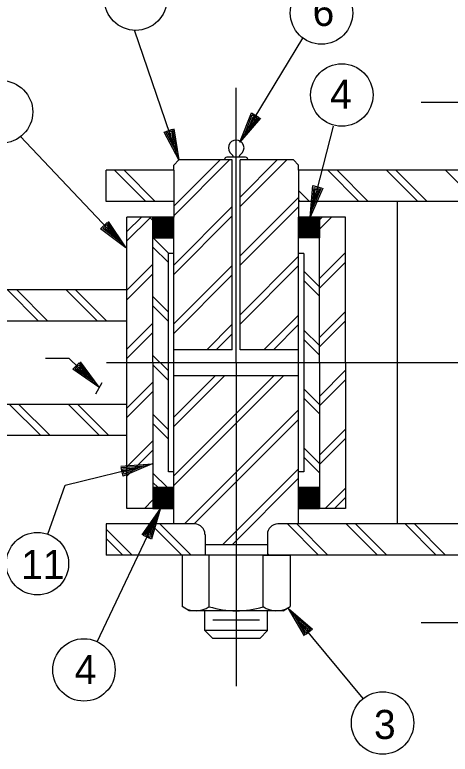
# Model space of a CAD drawing. Extents: x -0.2 to 13.5, y -0.2 to 9.5.
# Drawn here: x 2.351 to 3.223, y 1.127 to 2.607 of the extents above; entities that cross this region are included whole.
import ezdxf

# ---------------------------------------------------------------- set-up
doc = ezdxf.new("R2010")
doc.units = 0
for name, color, linetype in [('Level 2', 7, 'Continuous'), ('Level 3', 7, 'Continuous'), ('Level 50', 7, 'Continuous')]:
    doc.layers.add(name, color=color, linetype=linetype)

msp = doc.modelspace()

# ---------------------------------------------------------------- linework, layer by layer
at = {"layer": 'Level 2'}
for p, q in [((2.7941, 1.9106), (2.7941, 2.4612)), ((4.7037, 2.4315), (3.1643, 2.4315)), ((2.6795, 2.3169), (2.6691, 2.3065)), ((2.7863, 2.3169), (2.6795, 2.3169)), ((2.7709, 2.3169), (2.7709, 2.3179)), ((2.813, 2.322), (2.775, 2.322)), ((2.7863, 1.9367), (2.7863, 2.3169)), ((2.7941, 2.322), (2.7941, 2.322)), ((2.7941, 2.322), (2.7941, 2.322)), ((2.8019, 1.9367), (2.8019, 2.3169)), ((2.9086, 2.3169), (2.8019, 2.3169)), ((2.8172, 2.3169), (2.8172, 2.3179)), ((2.9086, 2.3169), (2.9191, 2.3065)), ((2.5336, 2.2336), (2.5336, 2.2961)), ((2.6691, 2.2961), (2.5336, 2.2961)), ((2.6691, 2.2961), (2.6691, 2.3065)), ((2.6691, 2.2961), (2.6691, 2.2023)), ((2.9191, 2.2961), (2.9191, 2.3065)), ((2.9191, 2.2961), (2.9191, 2.2023)), ((3.4503, 2.2961), (2.9191, 2.2961)), ((2.6691, 2.2336), (2.5336, 2.2336)), ((3.4503, 2.2336), (2.9191, 2.2336)), ((3.117, 1.5877), (3.117, 2.2336)), ((2.5753, 1.619), (2.5753, 2.2023)), ((2.6691, 2.2023), (2.5753, 2.2023)), ((2.6274, 1.9106), (2.6274, 2.2023)), ((2.6691, 1.5877), (2.6691, 2.2023)), ((3.0128, 2.2023), (2.9191, 2.2023)), ((2.9191, 1.5877), (2.9191, 2.2023)), ((2.9607, 1.9106), (2.9607, 2.2023)), ((3.0128, 1.9106), (3.0128, 2.2023)), ((2.6691, 2.1606), (2.6274, 2.1606)), ((2.9607, 2.1606), (2.9191, 2.1606)), ((2.6586, 1.6919), (2.6586, 2.1294)), ((2.6691, 2.1294), (2.6586, 2.1294)), ((2.9295, 2.1294), (2.9191, 2.1294)), ((2.9295, 2.1294), (2.9295, 1.6919)), ((2.5753, 2.0565), (2.1899, 2.0565)), ((2.5753, 1.994), (2.1899, 1.994)), ((2.7863, 1.9367), (2.6691, 1.9367)), ((2.9191, 1.9367), (2.8019, 1.9367)), ((4.53, 1.9106), (2.534, 1.9106)), ((2.6274, 1.9106), (2.6274, 1.619)), ((2.7941, 1.9106), (2.7941, 1.2627)), ((2.9607, 1.9106), (2.9607, 1.619)), ((3.0128, 1.9106), (3.0128, 1.619)), ((2.9191, 1.8846), (2.6691, 1.8846)), ((2.5753, 1.8273), (2.1899, 1.8273)), ((2.5753, 1.7648), (2.1899, 1.7648)), ((2.6691, 1.6919), (2.6586, 1.6919)), ((2.9295, 1.6919), (2.9191, 1.6919)), ((2.6691, 1.6606), (2.6274, 1.6606)), ((2.9607, 1.6606), (2.9191, 1.6606)), ((2.6691, 1.619), (2.5753, 1.619)), ((3.0128, 1.619), (2.9191, 1.619)), ((2.5336, 1.5877), (2.5336, 1.5252)), ((2.7107, 1.5877), (2.5336, 1.5877)), ((3.4503, 1.5877), (2.8774, 1.5877)), ((2.7316, 1.5669), (2.7316, 1.5252)), ((2.8566, 1.5669), (2.8566, 1.5252)), ((2.8566, 1.5461), (2.7316, 1.5461)), ((3.4503, 1.5252), (2.5336, 1.5252)), ((2.9503, 1.5252), (2.6378, 1.5252)), ((2.6857, 1.5252), (2.6857, 1.4224)), ((2.7398, 1.4221), (2.7398, 1.5252)), ((2.8476, 1.5252), (2.9024, 1.5252)), ((2.8483, 1.4221), (2.8483, 1.5252)), ((2.9024, 1.5252), (2.9024, 1.4224)), ((2.7002, 1.4139), (2.6857, 1.4224)), ((2.8879, 1.4139), (2.9024, 1.4224)), ((2.8879, 1.4139), (2.7002, 1.4139)), ((2.7313, 1.3742), (2.7313, 1.4139)), ((2.8568, 1.3742), (2.8568, 1.4139)), ((2.8409, 1.3953), (2.7476, 1.3953)), ((4.7037, 1.3898), (3.1643, 1.3898)), ((2.7313, 1.3742), (2.747, 1.3586)), ((2.8568, 1.3742), (2.7313, 1.3742)), ((2.8568, 1.3742), (2.8411, 1.3586)), ((2.8411, 1.3586), (2.747, 1.3586)), ((2.8411, 1.3586), (2.747, 1.3586)), ((2.8409, 1.3586), (2.7476, 1.3586))]:
    msp.add_line(p, q, dxfattribs=at)
for points in [[(2.6691, 2.2051), (2.7808, 2.3169)], [(2.6691, 2.224), (2.7619, 2.3169)], [(2.8019, 2.2236), (2.8952, 2.3169)], [(2.8019, 2.2424), (2.8763, 2.3169)], [(2.613, 2.2336), (2.5505, 2.2961)], [(2.6319, 2.2336), (2.5694, 2.2961)], [(2.6691, 2.2953), (2.6684, 2.2961)], [(3.0398, 2.2335), (2.9773, 2.2961)], [(3.0587, 2.2335), (2.9962, 2.2961)], [(3.1577, 2.2336), (3.0952, 2.2961)], [(3.1766, 2.2336), (3.114, 2.2961)], [(3.2755, 2.2336), (3.213, 2.2961)], [(2.9408, 2.2336), (2.9191, 2.2553)], [(2.8019, 2.1246), (2.9191, 2.2418)], [(2.922, 2.2335), (2.9191, 2.2365)], [(2.6691, 2.1061), (2.7863, 2.2233)], [(2.8019, 2.1057), (2.9191, 2.2229)], [(2.5753, 2.1546), (2.6231, 2.2023)], [(2.5753, 2.1734), (2.6042, 2.2023)], [(2.6274, 2.1955), (2.6206, 2.2023)], [(2.6274, 2.2017), (2.6691, 2.2017)], [(2.6274, 2.2005), (2.6691, 2.2005)], [(2.6274, 2.1992), (2.6691, 2.1992)], [(2.6274, 2.198), (2.6691, 2.198)], [(2.6274, 2.1967), (2.6691, 2.1967)], [(2.6274, 2.1955), (2.6691, 2.1955)], [(2.6274, 2.1942), (2.6691, 2.1942)], [(2.6274, 2.193), (2.6691, 2.193)], [(2.6274, 2.1917), (2.6691, 2.1917)], [(2.6691, 2.0873), (2.7863, 2.2045)], [(2.9191, 2.2018), (2.9607, 2.2018)], [(2.9191, 2.2005), (2.9607, 2.2005)], [(2.9191, 2.1993), (2.9607, 2.1993)], [(2.9191, 2.198), (2.9607, 2.198)], [(2.9191, 2.1968), (2.9607, 2.1968)], [(2.9191, 2.1955), (2.9607, 2.1955)], [(2.9191, 2.1943), (2.9607, 2.1943)], [(2.9191, 2.193), (2.9607, 2.193)], [(2.9191, 2.1918), (2.9607, 2.1918)], [(2.9607, 2.178), (2.985, 2.2023)], [(2.9607, 2.1969), (2.9661, 2.2023)], [(2.6274, 2.1905), (2.6691, 2.1905)], [(2.6274, 2.1892), (2.6691, 2.1892)], [(2.6274, 2.188), (2.6691, 2.188)], [(2.6274, 2.1867), (2.6691, 2.1867)], [(2.6274, 2.1855), (2.6691, 2.1855)], [(2.6274, 2.1842), (2.6691, 2.1842)], [(2.6274, 2.183), (2.6691, 2.183)], [(2.6274, 2.1817), (2.6691, 2.1817)], [(2.6274, 2.1805), (2.6691, 2.1805)], [(2.6274, 2.1792), (2.6691, 2.1792)], [(2.6274, 2.178), (2.6691, 2.178)], [(2.6274, 2.1767), (2.6691, 2.1767)], [(2.9191, 2.1905), (2.9607, 2.1905)], [(2.9191, 2.1893), (2.9607, 2.1893)], [(2.9191, 2.188), (2.9607, 2.188)], [(2.9191, 2.1868), (2.9607, 2.1868)], [(2.9191, 2.1855), (2.9607, 2.1855)], [(2.9191, 2.1843), (2.9607, 2.1843)], [(2.9191, 2.183), (2.9607, 2.183)], [(2.9191, 2.1818), (2.9607, 2.1818)], [(2.9191, 2.1805), (2.9607, 2.1805)], [(2.9191, 2.1793), (2.9607, 2.1793)], [(2.9191, 2.178), (2.9607, 2.178)], [(2.9191, 2.1768), (2.9607, 2.1768)], [(2.6274, 2.1755), (2.6691, 2.1755)], [(2.6274, 2.1742), (2.6691, 2.1742)], [(2.6274, 2.173), (2.6691, 2.173)], [(2.6274, 2.1717), (2.6691, 2.1717)], [(2.6274, 2.1705), (2.6691, 2.1705)], [(2.6274, 2.1692), (2.6691, 2.1692)], [(2.6274, 2.168), (2.6691, 2.168)], [(2.6274, 2.1667), (2.6691, 2.1667)], [(2.6274, 2.1655), (2.6691, 2.1655)], [(2.6274, 2.1642), (2.6691, 2.1642)], [(2.6274, 2.163), (2.6691, 2.163)], [(2.9191, 2.1755), (2.9607, 2.1755)], [(2.9191, 2.1743), (2.9607, 2.1743)], [(2.9191, 2.173), (2.9607, 2.173)], [(2.9191, 2.1718), (2.9607, 2.1718)], [(2.9191, 2.1705), (2.9607, 2.1705)], [(2.9191, 2.1693), (2.9607, 2.1693)], [(2.9191, 2.168), (2.9607, 2.168)], [(2.9191, 2.1668), (2.9607, 2.1668)], [(2.9191, 2.1655), (2.9607, 2.1655)], [(2.9191, 2.1643), (2.9607, 2.1643)], [(2.9191, 2.163), (2.9607, 2.163)], [(2.9191, 2.1618), (2.9607, 2.1618)], [(2.6274, 2.1617), (2.6691, 2.1617)], [(2.6591, 2.1294), (2.6279, 2.1606)], [(2.6586, 2.111), (2.6274, 2.1423)], [(2.8019, 2.0067), (2.9191, 2.1239)], [(2.9607, 2.079), (3.0128, 2.1311)], [(2.5753, 2.0556), (2.6274, 2.1077)], [(2.6691, 1.9883), (2.7863, 2.1055)], [(2.8019, 1.9879), (2.9191, 2.1051)], [(2.9607, 2.0602), (3.0128, 2.1123)], [(2.5753, 2.0367), (2.6274, 2.0888)], [(2.9607, 2.0627), (2.9295, 2.0939)], [(2.6691, 1.9694), (2.7863, 2.0866)], [(2.9607, 2.0438), (2.9295, 2.0751)], [(2.3982, 1.994), (2.3357, 2.0565)], [(2.417, 1.994), (2.3545, 2.0565)], [(2.516, 1.994), (2.4535, 2.0565)], [(2.5349, 1.994), (2.4724, 2.0565)], [(2.6586, 2.012), (2.6274, 2.0433)], [(2.6586, 1.9931), (2.6274, 2.0244)], [(2.8497, 1.9367), (2.9191, 2.0061)], [(2.9607, 1.9612), (3.0128, 2.0133)], [(2.5753, 1.9377), (2.6274, 1.9898)], [(2.7353, 1.9367), (2.7863, 1.9876)], [(2.8685, 1.9367), (2.9191, 1.9872)], [(2.9607, 1.9423), (3.0128, 1.9944)], [(2.5753, 1.9189), (2.6274, 1.9709)], [(2.9607, 1.9448), (2.9295, 1.9761)], [(2.7541, 1.9367), (2.7863, 1.9688)], [(2.9607, 1.926), (2.9295, 1.9572)], [(2.6586, 1.8941), (2.6274, 1.9254)], [(2.6586, 1.8753), (2.6274, 1.9066)], [(2.9607, 1.8433), (3.0128, 1.8954)], [(2.6691, 1.6651), (2.8886, 1.8846)], [(2.6691, 1.7829), (2.7707, 1.8846)], [(2.6691, 1.6839), (2.8697, 1.8846)], [(2.6691, 1.8018), (2.7519, 1.8846)], [(2.5753, 1.8199), (2.6274, 1.8719)], [(2.9607, 1.8245), (3.0128, 1.8766)], [(2.5753, 1.801), (2.6274, 1.8531)], [(2.9607, 1.827), (2.9295, 1.8582)], [(2.9607, 1.8081), (2.9295, 1.8394)], [(2.4025, 1.7648), (2.34, 1.8273)], [(2.4214, 1.7648), (2.3589, 1.8273)], [(2.5204, 1.7648), (2.4579, 1.8273)], [(2.5392, 1.7648), (2.4767, 1.8273)], [(2.6586, 1.7763), (2.6274, 1.8076)], [(2.6907, 1.5877), (2.9191, 1.8161)], [(2.7096, 1.5877), (2.9191, 1.7972)], [(2.6586, 1.7574), (2.6274, 1.7887)], [(2.9607, 1.7255), (3.0128, 1.7776)], [(2.5753, 1.702), (2.6274, 1.7541)], [(2.9607, 1.7066), (3.0128, 1.7587)], [(2.5753, 1.6832), (2.6274, 1.7352)], [(2.9607, 1.7091), (2.9295, 1.7404)], [(2.9607, 1.6903), (2.9295, 1.7215)], [(2.6565, 1.6606), (2.6274, 1.6897)], [(2.7669, 1.5461), (2.9191, 1.6982)], [(2.7858, 1.5461), (2.9191, 1.6794)], [(2.6376, 1.6606), (2.6274, 1.6708)], [(2.6274, 1.6594), (2.6691, 1.6594)], [(2.9191, 1.6606), (2.9607, 1.6606)], [(2.9191, 1.6594), (2.9607, 1.6594)], [(2.9721, 1.619), (3.0128, 1.6597)], [(2.6274, 1.6582), (2.6691, 1.6582)], [(2.6274, 1.6569), (2.6691, 1.6569)], [(2.6274, 1.6557), (2.6691, 1.6557)], [(2.6274, 1.6544), (2.6691, 1.6544)], [(2.6274, 1.6532), (2.6691, 1.6532)], [(2.6274, 1.6519), (2.6691, 1.6519)], [(2.6274, 1.6507), (2.6691, 1.6507)], [(2.6274, 1.6494), (2.6691, 1.6494)], [(2.6274, 1.6482), (2.6691, 1.6482)], [(2.6274, 1.6469), (2.6691, 1.6469)], [(2.6274, 1.6457), (2.6691, 1.6457)], [(2.6274, 1.6444), (2.6691, 1.6444)], [(2.9191, 1.6581), (2.9607, 1.6581)], [(2.9191, 1.6569), (2.9607, 1.6569)], [(2.9191, 1.6556), (2.9607, 1.6556)], [(2.9191, 1.6544), (2.9607, 1.6544)], [(2.9191, 1.6531), (2.9607, 1.6531)], [(2.9191, 1.6519), (2.9607, 1.6519)], [(2.9191, 1.6506), (2.9607, 1.6506)], [(2.9191, 1.6494), (2.9607, 1.6494)], [(2.9191, 1.6481), (2.9607, 1.6481)], [(2.9191, 1.6469), (2.9607, 1.6469)], [(2.9191, 1.6456), (2.9607, 1.6456)], [(2.9191, 1.6444), (2.9607, 1.6444)], [(2.6101, 1.619), (2.6274, 1.6363)], [(2.6274, 1.6432), (2.6691, 1.6432)], [(2.6274, 1.6419), (2.6691, 1.6419)], [(2.6274, 1.6407), (2.6691, 1.6407)], [(2.6274, 1.6394), (2.6691, 1.6394)], [(2.6274, 1.6382), (2.6691, 1.6382)], [(2.6274, 1.6369), (2.6691, 1.6369)], [(2.6274, 1.6357), (2.6691, 1.6357)], [(2.6274, 1.6344), (2.6691, 1.6344)], [(2.6274, 1.6332), (2.6691, 1.6332)], [(2.6274, 1.6319), (2.6691, 1.6319)], [(2.6274, 1.6307), (2.6691, 1.6307)], [(2.6274, 1.6294), (2.6691, 1.6294)], [(2.9191, 1.6431), (2.9607, 1.6431)], [(2.9191, 1.6419), (2.9607, 1.6419)], [(2.9191, 1.6406), (2.9607, 1.6406)], [(2.9191, 1.6394), (2.9607, 1.6394)], [(2.9191, 1.6381), (2.9607, 1.6381)], [(2.9191, 1.6369), (2.9607, 1.6369)], [(2.9191, 1.6356), (2.9607, 1.6356)], [(2.9191, 1.6344), (2.9607, 1.6344)], [(2.9191, 1.6331), (2.9607, 1.6331)], [(2.9191, 1.6319), (2.9607, 1.6319)], [(2.9191, 1.6306), (2.9607, 1.6306)], [(2.9191, 1.6294), (2.9607, 1.6294)], [(2.9909, 1.619), (3.0128, 1.6409)], [(2.6274, 1.6282), (2.6691, 1.6282)], [(2.6274, 1.6269), (2.6691, 1.6269)], [(2.6274, 1.6257), (2.6691, 1.6257)], [(2.6274, 1.6244), (2.6691, 1.6244)], [(2.6274, 1.6232), (2.6691, 1.6232)], [(2.6274, 1.6219), (2.6691, 1.6219)], [(2.6274, 1.6207), (2.6691, 1.6207)], [(2.6274, 1.6194), (2.6691, 1.6194)], [(2.9191, 1.6281), (2.9607, 1.6281)], [(2.9191, 1.6269), (2.9607, 1.6269)], [(2.9191, 1.6256), (2.9607, 1.6256)], [(2.9191, 1.6244), (2.9607, 1.6244)], [(2.9191, 1.6231), (2.9607, 1.6231)], [(2.9191, 1.6219), (2.9607, 1.6219)], [(2.9191, 1.6206), (2.9607, 1.6206)], [(2.9191, 1.6194), (2.9607, 1.6194)], [(2.6849, 1.5252), (2.6224, 1.5877)], [(2.7038, 1.5252), (2.6412, 1.5877)], [(2.959, 1.5252), (2.8965, 1.5877)], [(2.9778, 1.5252), (2.9153, 1.5877)], [(3.0768, 1.5252), (3.0143, 1.5877)], [(3.0957, 1.5252), (3.0332, 1.5877)], [(3.1947, 1.5252), (3.1322, 1.5877)], [(3.2135, 1.5252), (3.151, 1.5877)], [(2.5859, 1.5252), (2.5336, 1.5775)], [(2.567, 1.5252), (2.5336, 1.5586)], [(2.86, 1.5252), (2.8566, 1.5286)]]:
    msp.add_lwpolyline(points, dxfattribs=at)
for points in [[(2.6274, 2.2023), (2.6274, 2.1606), (2.6691, 2.1606), (2.6691, 2.2023)], [(2.9607, 2.2023), (2.9607, 2.1606), (2.9191, 2.1606), (2.9191, 2.2023)], [(2.6274, 1.6606), (2.6274, 1.619), (2.6691, 1.619), (2.6691, 1.6606)], [(2.9191, 1.6606), (2.9191, 1.619), (2.9607, 1.619), (2.9607, 1.6606)]]:
    msp.add_lwpolyline(points, close=True, dxfattribs=at)
for centre, radius, start, end in [((2.7941, 2.3408), 0.0156, 306.8699, 233.1301), ((2.7784, 2.3199), 0.0104, 11.771, 53.1301), ((2.8097, 2.3199), 0.0104, 126.8699, 168.229), ((2.775, 2.3179), 0.00417, 90, 180), ((2.813, 2.3179), 0.00417, 0, 90), ((2.7107, 1.5669), 0.0208, 0, 90), ((2.8774, 1.5669), 0.0208, 90, 180), ((2.7131, 1.4609), 0.047, 239.7124, 304.511), ((2.7948, 1.6021), 0.1882, 253.0184, 286.4966), ((2.875, 1.4609), 0.047, 235.489, 300.2876)]:
    msp.add_arc(centre, radius, start, end, dxfattribs=at)
at = {"layer": 'Level 3'}
for p, q in [((2.6795, 2.3169), (2.5903, 2.5768)), ((2.8015, 2.352), (2.9272, 2.5605)), ((2.9419, 2.2023), (2.9887, 2.3841)), ((2.5729, 2.1408), (2.3617, 2.364)), ((2.8105, 2.3668), (2.8105, 2.3668)), ((2.8015, 2.352), (2.8015, 2.352)), ((2.6739, 2.3333), (2.6739, 2.3333)), ((2.6795, 2.3169), (2.6795, 2.3169)), ((2.9462, 2.2191), (2.9462, 2.2191)), ((2.9419, 2.2023), (2.9419, 2.2023)), ((2.561, 2.1534), (2.561, 2.1534)), ((2.5729, 2.1408), (2.5729, 2.1408)), ((2.4119, 1.9199), (2.4588, 1.9199)), ((2.4588, 1.9199), (2.5191, 1.8616)), ((2.5066, 1.8736), (2.5066, 1.8736)), ((2.5128, 1.8481), (2.5253, 1.8709)), ((2.5191, 1.8616), (2.5191, 1.8616)), ((2.4518, 1.6655), (2.626, 1.7084)), ((2.4169, 1.5671), (2.4518, 1.6655)), ((2.5158, 1.352), (2.6418, 1.6177)), ((2.6418, 1.6177), (2.6418, 1.6177)), ((2.6344, 1.6021), (2.6344, 1.6021)), ((3.0484, 1.2382), (2.8991, 1.4183)), ((2.8991, 1.4183), (2.8991, 1.4183)), ((2.9102, 1.405), (2.9102, 1.405))]:
    msp.add_line(p, q, dxfattribs=at)
for points in [[(2.8426, 2.4001), (2.8015, 2.352), (2.8249, 2.4107), (2.84, 2.4016), (2.8105, 2.3668), (2.8263, 2.4067), (2.836, 2.4009), (2.8191, 2.3811), (2.8278, 2.4027), (2.8318, 2.4003), (2.828, 2.396)], [(2.669, 2.3792), (2.6795, 2.3169), (2.6495, 2.3725), (2.6662, 2.3782), (2.6739, 2.3333), (2.6535, 2.3711), (2.6642, 2.3747), (2.6684, 2.349), (2.6575, 2.3696), (2.6619, 2.3711), (2.6628, 2.3654)], [(2.9674, 2.2601), (2.9419, 2.2023), (2.9474, 2.2652), (2.9645, 2.2608), (2.9462, 2.2191), (2.95, 2.2618), (2.961, 2.259), (2.9504, 2.2352), (2.9525, 2.2584), (2.9571, 2.2572), (2.9547, 2.252)], [(2.5376, 2.1932), (2.5729, 2.1408), (2.5226, 2.179), (2.5354, 2.1911), (2.561, 2.1534), (2.5268, 2.1793), (2.5351, 2.1871), (2.5496, 2.1655), (2.5311, 2.1797), (2.5345, 2.1829), (2.5377, 2.1781)], [(2.4814, 1.9123), (2.5191, 1.8616), (2.4671, 1.8975), (2.4794, 1.9102), (2.5066, 1.8736), (2.4713, 1.898), (2.4792, 1.9062), (2.4946, 1.8852), (2.4755, 1.8986), (2.4788, 1.9019), (2.4822, 1.8973)], [(2.6058, 1.5658), (2.6418, 1.6177), (2.6245, 1.557), (2.6085, 1.5646), (2.6344, 1.6021), (2.6226, 1.5608), (2.6124, 1.5657), (2.6273, 1.587), (2.6207, 1.5647), (2.6165, 1.5667), (2.6198, 1.5714)], [(2.9309, 1.3637), (2.8991, 1.4183), (2.9468, 1.3769), (2.9332, 1.3657), (2.9102, 1.405), (2.9426, 1.3769), (2.9338, 1.3696), (2.9208, 1.3921), (2.9383, 1.3768), (2.9347, 1.3738), (2.9319, 1.3788)]]:
    msp.add_lwpolyline(points, dxfattribs=at)
for centre in [(2.5927, 2.6387), (2.9649, 2.6109), (3.0056, 2.4468), (2.3241, 2.4129), (2.396, 1.5082), (2.4891, 1.2955), (3.0872, 1.1892)]:
    msp.add_circle(centre, 0.0625, dxfattribs=at)
at = {"layer": 'Level 50'}
for p, q in [((2.6091, 1.7043), (2.6091, 1.7043)), ((2.626, 1.7084), (2.626, 1.7084))]:
    msp.add_line(p, q, dxfattribs=at)
msp.add_lwpolyline([(2.563, 1.7035), (2.626, 1.7084), (2.5679, 1.6834), (2.5637, 1.7006), (2.6091, 1.7043), (2.5697, 1.6873), (2.567, 1.6983), (2.593, 1.7003), (2.5715, 1.6912), (2.5704, 1.6957), (2.5761, 1.6961)], dxfattribs=at)

# ---------------------------------------------------------------- texts
at = {"layer": 'Level 3'}
for s, height, p in [('6', 0.0583, (2.9471, 2.585)), ('4', 0.0583, (2.9822, 2.4191)), ('11', 0.05833, (2.3634, 1.4774)), ('4', 0.0583, (2.4706, 1.2671)), ('3', 0.0583, (3.07, 1.1571))]:
    msp.add_text(s, height=height, dxfattribs=at).set_placement(p)

doc.saveas('drawing.dxf')
